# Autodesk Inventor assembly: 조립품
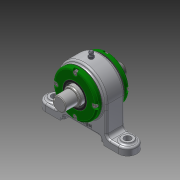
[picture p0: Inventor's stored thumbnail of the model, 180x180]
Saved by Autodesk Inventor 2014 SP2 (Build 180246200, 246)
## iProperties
Created: 2019-05
Part Number: 조립품
Document SubType Name: Assembly
Designer: gs
Author: gs
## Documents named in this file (11)
- C:\Users\gs\Desktop\490504V1042\조립품.iam
- C:\Users\gs\Desktop\490504V1042\본체.ipt
- C:\Users\gs\Desktop\490504V1042\커버.ipt
- C:\Users\gs\Desktop\490504V1042\축.ipt
- C:\Users\gs\Desktop\490504V1042\앵귤러 볼 베어링 7205.ipt
- C:\Users\gs\Desktop\490504V1042\오일 실 28 40 5 B.ipt
- C:\Users\gs\Desktop\490504V1042\개스킷.ipt
- C:\Users\gs\Desktop\490504V1042\그리스니플개스킷.ipt
- C:\Users\gs\Desktop\490504V1042\그리스니플 M6.ipt
- 그리스니플  M6.ipt
- C:\Users\gs\Desktop\490504V1042\볼트 M4.ipt
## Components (4 placed, 3 different names)
1. 개스킷:1
2. 개스킷:2
3. 그리스니플개스킷:1
4. 그리스니플  M6:1
